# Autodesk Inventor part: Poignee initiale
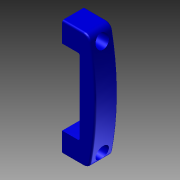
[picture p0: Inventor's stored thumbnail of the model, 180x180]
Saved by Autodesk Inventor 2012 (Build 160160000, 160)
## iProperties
Created: 2011-01
Part Number: Poignee initiale
Document SubType Name: Modeling
Designer: eric
Density: 1 g/cm^3
Mass: 40.4489 g
Surface Area: 162.892 cm^2
Volume: 40.4489 cm^3
Material: Par défaut
Author: eric
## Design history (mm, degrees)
feature "Base1"
sketch "Esquisse1"
  geometry: L1 (0, 20)-(0, 0) reference; L2 (0, 0)-(20, 0) reference; L3 (20, 0)-(20, 20) reference; L4 (20, 20)-(0, 20) reference; C1 r 7.5 at (9, 10) reference; 1 further point
extrude "Extrusion1" join sketch "Esquisse1" stored distance "d0" = 10; taper "d1" = 0 deg
fillet "Congé1" dims "d2" = 8
sketch "Esquisse2"
  geometry: L1 (0, 20)-(0, 0) reference; L2 (-20, 20)-(0, 20) reference; L3 (-20, 0)-(-20, 20) reference; L4 (0, 0)-(-20, 0) reference; C1 r 7.5 at (-9, 10) reference; 1 further point
extrude "Extrusion2" join sketch "Esquisse2" stored distance "d3" = 10; taper "d4" = 0 deg
fillet "Congé2" dims "d5" = 8
node "Plan de construction1"
sketch "Esquisse3"
  geometry: L1 (-86, 26)-(-86, 0) reference; L2 (0, 26)-(0, 0) reference; L3 (-84.269, 26)-(-1.731, 26) reference; L4 (-84.269, 0)-(-1.731, 0) reference; L5 (-1.731, 26)-(0, 26) reference; L6 (-86, 0)-(-84.269, 0) reference; L7 (-86, 26)-(-84.269, 26) reference; L8 (-1.731, 0)-(0, 0) reference; 1 further point
extrude "Extrusion3" join sketch "Esquisse3" stored distance "d7" = 10; taper "d8" = 0 deg
fillet "Congé3" dims "d9" = 2
node "Corps solides"
node "Corps surfaciques"
node "Solide1"
